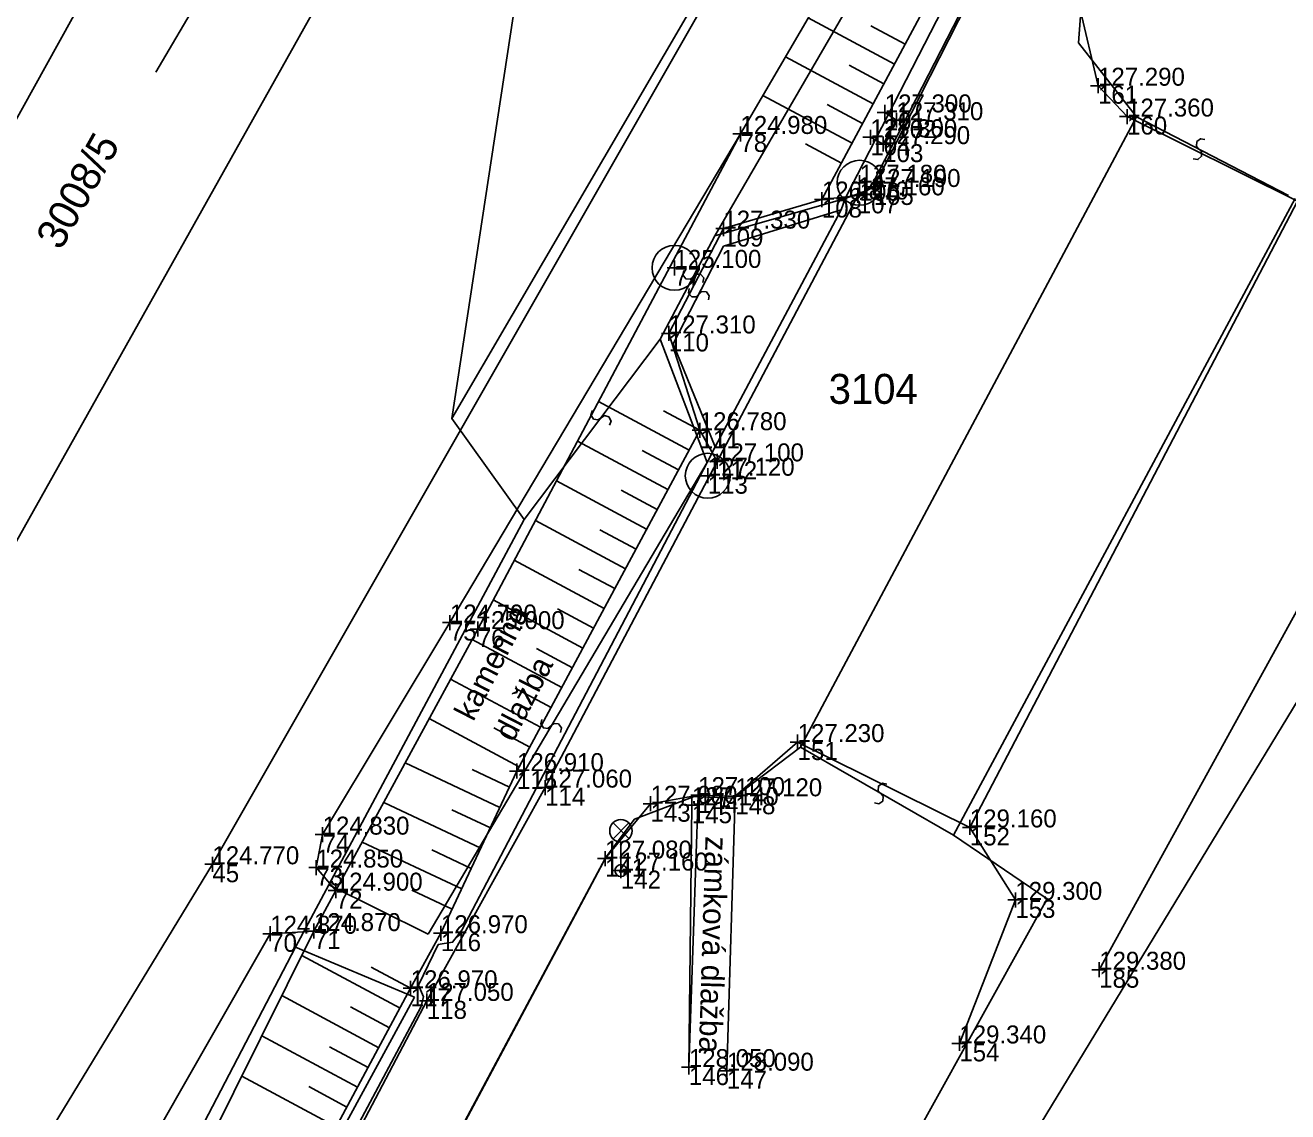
# Model space of a CAD drawing. Extents: x -747268 to -747054, y -964730 to -964532.
# Drawn here: x -747222.18 to -747180.02, y -964669.15 to -964632.88 of the extents above; entities that cross this region are included whole.
import ezdxf

# ---------------------------------------------------------------- set-up
doc = ezdxf.new("R2010")
doc.units = 0
for name, color, linetype in [('Body polohopisu', 7, 'Continuous'), ('Doplňkové značky', 7, 'Continuous'), ('KM', 7, 'Continuous'), ('Ploty_opěrné zdi', 7, 'Continuous'), ('Popisy objektů_povrchů', 7, 'Continuous'), ('Rozhraní ploch', 7, 'Continuous'), ('Vnitřní kresba', 7, 'Continuous'), ('Výškopis', 7, 'Continuous'), ('Výšky bodů', 7, 'Continuous'), ('Značky IS', 7, 'Continuous'), ('Čísla bodů', 7, 'Continuous')]:
    doc.layers.add(name, color=color, linetype=linetype)

msp = doc.modelspace()

# ---------------------------------------------------------------- linework, layer by layer
at = {"layer": 'Body polohopisu'}
for p, q in [((-747186.36, -964634.9), (-747186.36, -964634.65)), ((-747186.36, -964634.9), (-747186.61, -964634.9)), ((-747186.36, -964634.9), (-747186.11, -964634.9)), ((-747186.36, -964634.9), (-747186.36, -964635.15)), ((-747193.48, -964635.79), (-747193.48, -964635.54)), ((-747185.39, -964635.93), (-747185.39, -964635.68)), ((-747193.48, -964635.79), (-747193.73, -964635.79)), ((-747193.48, -964635.79), (-747193.23, -964635.79)), ((-747193.48, -964635.79), (-747193.48, -964636.04)), ((-747193.09, -964636.05), (-747193.34, -964636.05)), ((-747193.09, -964636.05), (-747193.09, -964635.8)), ((-747193.09, -964636.05), (-747192.84, -964636.05)), ((-747193.09, -964636.05), (-747193.09, -964636.3)), ((-747185.39, -964635.93), (-747185.64, -964635.93)), ((-747185.39, -964635.93), (-747185.14, -964635.93)), ((-747185.39, -964635.93), (-747185.39, -964636.18)), ((-747198.3, -964636.51), (-747198.55, -964636.51)), ((-747198.3, -964636.51), (-747198.3, -964636.26)), ((-747198.3, -964636.51), (-747198.05, -964636.51)), ((-747198.3, -964636.51), (-747198.3, -964636.76)), ((-747193.96, -964636.62), (-747193.96, -964636.37)), ((-747193.96, -964636.62), (-747194.21, -964636.62)), ((-747193.96, -964636.62), (-747193.71, -964636.62)), ((-747193.96, -964636.62), (-747193.96, -964636.87)), ((-747193.53, -964636.85), (-747193.78, -964636.85)), ((-747193.53, -964636.85), (-747193.53, -964636.6)), ((-747193.53, -964636.85), (-747193.28, -964636.85)), ((-747193.53, -964636.85), (-747193.53, -964637.1)), ((-747194.32, -964638.14), (-747194.57, -964638.14)), ((-747194.32, -964638.14), (-747194.32, -964637.89)), ((-747194.32, -964638.14), (-747194.07, -964638.14)), ((-747194.32, -964638.14), (-747194.32, -964638.39)), ((-747193.85, -964638.28), (-747193.85, -964638.03)), ((-747195.58, -964638.7), (-747195.58, -964638.45)), ((-747194.38, -964638.56), (-747194.63, -964638.56)), ((-747194.38, -964638.56), (-747194.38, -964638.31)), ((-747194.38, -964638.56), (-747194.13, -964638.56)), ((-747194.38, -964638.56), (-747194.38, -964638.81)), ((-747193.85, -964638.28), (-747194.1, -964638.28)), ((-747193.85, -964638.28), (-747193.6, -964638.28)), ((-747193.85, -964638.28), (-747193.85, -964638.53)), ((-747195.58, -964638.7), (-747195.83, -964638.7)), ((-747195.58, -964638.7), (-747195.33, -964638.7)), ((-747195.58, -964638.7), (-747195.58, -964638.95)), ((-747198.87, -964639.67), (-747198.87, -964639.42)), ((-747198.87, -964639.67), (-747199.12, -964639.67)), ((-747198.87, -964639.67), (-747198.62, -964639.67)), ((-747198.87, -964639.67), (-747198.87, -964639.92)), ((-747200.5, -964640.98), (-747200.5, -964640.73)), ((-747200.5, -964640.98), (-747200.75, -964640.98)), ((-747200.5, -964640.98), (-747200.25, -964640.98)), ((-747200.5, -964640.98), (-747200.5, -964641.23)), ((-747200.69, -964643.17), (-747200.94, -964643.17)), ((-747200.69, -964643.17), (-747200.69, -964642.92)), ((-747200.69, -964643.17), (-747200.44, -964643.17)), ((-747200.69, -964643.17), (-747200.69, -964643.42)), ((-747199.66, -964646.4), (-747199.66, -964646.15)), ((-747199.66, -964646.4), (-747199.91, -964646.4)), ((-747199.66, -964646.4), (-747199.41, -964646.4)), ((-747199.66, -964646.4), (-747199.66, -964646.65)), ((-747199.08, -964647.44), (-747199.33, -964647.44)), ((-747199.08, -964647.44), (-747199.08, -964647.19)), ((-747199.08, -964647.44), (-747198.83, -964647.44)), ((-747199.08, -964647.44), (-747199.08, -964647.69)), ((-747199.39, -964647.92), (-747199.64, -964647.92)), ((-747199.39, -964647.92), (-747199.39, -964647.67)), ((-747199.39, -964647.92), (-747199.14, -964647.92)), ((-747199.39, -964647.92), (-747199.39, -964648.17)), ((-747208, -964652.82), (-747208, -964652.57)), ((-747208, -964652.82), (-747208.25, -964652.82)), ((-747208, -964652.82), (-747207.75, -964652.82)), ((-747208, -964652.82), (-747208, -964653.07)), ((-747207.07, -964653.04), (-747207.07, -964652.79)), ((-747207.07, -964653.04), (-747207.32, -964653.04)), ((-747207.07, -964653.04), (-747206.82, -964653.04)), ((-747207.07, -964653.04), (-747207.07, -964653.29)), ((-747196.39, -964656.81), (-747196.39, -964656.56)), ((-747196.39, -964656.81), (-747196.64, -964656.81)), ((-747196.39, -964656.81), (-747196.14, -964656.81)), ((-747196.39, -964656.81), (-747196.39, -964657.06)), ((-747205.76, -964657.78), (-747205.76, -964657.53)), ((-747205.76, -964657.78), (-747206.01, -964657.78)), ((-747205.76, -964657.78), (-747205.51, -964657.78)), ((-747205.76, -964657.78), (-747205.76, -964658.03)), ((-747204.82, -964658.33), (-747205.07, -964658.33)), ((-747204.82, -964658.33), (-747204.82, -964658.08)), ((-747204.82, -964658.33), (-747204.57, -964658.33)), ((-747204.82, -964658.33), (-747204.82, -964658.58)), ((-747199.71, -964658.58), (-747199.71, -964658.33)), ((-747198.47, -964658.62), (-747198.47, -964658.37)), ((-747201.3, -964658.87), (-747201.55, -964658.87)), ((-747201.3, -964658.87), (-747201.3, -964658.62)), ((-747201.3, -964658.87), (-747201.05, -964658.87)), ((-747201.3, -964658.87), (-747201.3, -964659.12)), ((-747199.71, -964658.58), (-747199.96, -964658.58)), ((-747199.92, -964658.92), (-747199.92, -964658.67)), ((-747199.71, -964658.58), (-747199.46, -964658.58)), ((-747199.71, -964658.58), (-747199.71, -964658.83)), ((-747198.47, -964658.62), (-747198.72, -964658.62)), ((-747198.47, -964658.62), (-747198.22, -964658.62)), ((-747198.47, -964658.62), (-747198.47, -964658.87)), ((-747199.92, -964658.92), (-747200.17, -964658.92)), ((-747199.92, -964658.92), (-747199.67, -964658.92)), ((-747199.92, -964658.92), (-747199.92, -964659.17)), ((-747212.25, -964659.9), (-747212.25, -964659.65)), ((-747190.64, -964659.66), (-747190.89, -964659.66)), ((-747190.64, -964659.66), (-747190.64, -964659.41)), ((-747190.64, -964659.66), (-747190.39, -964659.66)), ((-747190.64, -964659.66), (-747190.64, -964659.91)), ((-747212.25, -964659.9), (-747212.5, -964659.9)), ((-747212.25, -964659.9), (-747212, -964659.9)), ((-747212.25, -964659.9), (-747212.25, -964660.15)), ((-747202.82, -964660.7), (-747202.82, -964660.45)), ((-747215.93, -964660.89), (-747216.18, -964660.89)), ((-747215.93, -964660.89), (-747215.93, -964660.64)), ((-747215.93, -964660.89), (-747215.68, -964660.89)), ((-747215.93, -964660.89), (-747215.93, -964661.14)), ((-747212.46, -964661), (-747212.71, -964661)), ((-747212.46, -964661), (-747212.46, -964660.75)), ((-747212.46, -964661), (-747212.21, -964661)), ((-747212.46, -964661), (-747212.46, -964661.25)), ((-747202.82, -964660.7), (-747203.07, -964660.7)), ((-747202.82, -964660.7), (-747202.57, -964660.7)), ((-747202.82, -964660.7), (-747202.82, -964660.95)), ((-747202.29, -964661.1), (-747202.29, -964660.85)), ((-747202.29, -964661.1), (-747202.54, -964661.1)), ((-747202.29, -964661.1), (-747202.04, -964661.1)), ((-747202.29, -964661.1), (-747202.29, -964661.35)), ((-747211.81, -964661.77), (-747212.06, -964661.77)), ((-747211.81, -964661.77), (-747211.81, -964661.52)), ((-747211.81, -964661.77), (-747211.56, -964661.77)), ((-747211.81, -964661.77), (-747211.81, -964662.02)), ((-747189.12, -964662.08), (-747189.12, -964661.83)), ((-747189.12, -964662.08), (-747189.37, -964662.08)), ((-747189.12, -964662.08), (-747188.87, -964662.08)), ((-747189.12, -964662.08), (-747189.12, -964662.33)), ((-747214, -964663.21), (-747214, -964662.96)), ((-747212.54, -964663.12), (-747212.54, -964662.87)), ((-747208.3, -964663.19), (-747208.3, -964662.94)), ((-747214, -964663.21), (-747214.25, -964663.21)), ((-747214, -964663.21), (-747213.75, -964663.21)), ((-747214, -964663.21), (-747214, -964663.46)), ((-747212.54, -964663.12), (-747212.79, -964663.12)), ((-747212.54, -964663.12), (-747212.29, -964663.12)), ((-747212.54, -964663.12), (-747212.54, -964663.37)), ((-747208.3, -964663.19), (-747208.55, -964663.19)), ((-747208.3, -964663.19), (-747208.05, -964663.19)), ((-747208.3, -964663.19), (-747208.3, -964663.44)), ((-747186.32, -964664.41), (-747186.32, -964664.16)), ((-747209.31, -964665.03), (-747209.31, -964664.78)), ((-747186.32, -964664.41), (-747186.57, -964664.41)), ((-747186.32, -964664.41), (-747186.07, -964664.41)), ((-747186.32, -964664.41), (-747186.32, -964664.66)), ((-747209.31, -964665.03), (-747209.56, -964665.03)), ((-747209.31, -964665.03), (-747209.06, -964665.03)), ((-747209.31, -964665.03), (-747209.31, -964665.28)), ((-747208.77, -964665.45), (-747208.77, -964665.2)), ((-747208.77, -964665.45), (-747209.02, -964665.45)), ((-747208.77, -964665.45), (-747208.52, -964665.45)), ((-747208.77, -964665.45), (-747208.77, -964665.7)), ((-747190.99, -964666.87), (-747191.24, -964666.87)), ((-747190.99, -964666.87), (-747190.99, -964666.62)), ((-747190.99, -964666.87), (-747190.74, -964666.87)), ((-747190.99, -964666.87), (-747190.99, -964667.12)), ((-747200.02, -964667.66), (-747200.27, -964667.66)), ((-747200.02, -964667.66), (-747200.02, -964667.41)), ((-747200.02, -964667.66), (-747199.77, -964667.66)), ((-747200.02, -964667.66), (-747200.02, -964667.91)), ((-747198.75, -964667.78), (-747198.75, -964667.53)), ((-747198.75, -964667.78), (-747199, -964667.78)), ((-747198.75, -964667.78), (-747198.5, -964667.78)), ((-747198.75, -964667.78), (-747198.75, -964668.03))]:
    msp.add_line(p, q, dxfattribs=at)
at = {"layer": 'Doplňkové značky'}
for p, q in [((-747202.554, -964660.038), (-747202.026, -964659.51)), ((-747202.018, -964660.035), (-747202.546, -964659.506)), ((-747202.29, -964660.15), (-747202.29, -964660.9))]:
    msp.add_line(p, q, dxfattribs=at)
for centre, radius in [((-747202.29, -964659.775), 0.375), ((-747202.29, -964661.1), 0.2)]:
    msp.add_circle(centre, radius, dxfattribs=at)
at = {"layer": 'KM'}
msp.add_line((-747217.82, -964634.444), (-747216.296, -964631.86), dxfattribs=at)
for points in [[(-747258.428, -964718.402), (-747225.89, -964656.18), (-747178.58, -964571.79), (-747161.768, -964542.826)], [(-747245.973, -964725.574), (-747237.39, -964710.13), (-747213.15, -964663.66), (-747212.04, -964661.58), (-747205.52, -964649.38), (-747207.93, -964646.01), (-747172.64, -964585.56), (-747171.18, -964583.16), (-747172.38, -964582.51), (-747172.75, -964582.31), (-747169.52, -964576.73), (-747168.08, -964577.53), (-747165.21, -964574.13), (-747160.86, -964564.14), (-747155.16, -964551.47), (-747155.48, -964551.37), (-747155.09, -964550.12), (-747154.28, -964550.33), (-747154.06, -964549.5), (-747153.365, -964547.044)], [(-747242.047, -964727.609), (-747230.16, -964705.36), (-747208.97, -964665.66), (-747208.88, -964665.32), (-747209.05, -964664.92), (-747208.39, -964663.57), (-747207.91, -964663.49), (-747207.6, -964663.09), (-747199.41, -964647.48), (-747199.14, -964646.95), (-747194.94, -964639.04), (-747194.8, -964638.66), (-747194.08, -964638.4), (-747193.89, -964638.17), (-747178.12, -964607.48), (-747165.52, -964582.92), (-747162.81, -964577.62), (-747161.38, -964574.2), (-747160.49, -964571.42), (-747153.77, -964550.39), (-747154.12, -964550.42), (-747153.81, -964549.44), (-747153.109, -964547.254)], [(-747149.729, -964549.086), (-747149.93, -964549.71), (-747150.35, -964549.8), (-747157.75, -964573.23), (-747158.53, -964575.6), (-747159.7, -964578.37), (-747163.23, -964585.33), (-747175.42, -964609.03), (-747186.84, -964631.22), (-747187.01, -964633.47), (-747185.08, -964635.94), (-747196.29, -964656.98), (-747198.54, -964658.68), (-747199.84, -964658.63), (-747201.84, -964659.38), (-747202.78, -964660.64), (-747203.73, -964662.42), (-747219.36, -964691.72)], [(-747179.78, -964638.67), (-747191.19, -964659.92), (-747188.06, -964662.04), (-747194.37, -964673.41)], [(-747170.03, -964639.52), (-747191.65, -964675.11), (-747205.07, -964701.27), (-747194.33, -964694.71), (-747168.43, -964681.69), (-747141.95, -964674.74), (-747119.57, -964669.71), (-747114.21, -964668.06), (-747110.99, -964665.85), (-747107.13, -964660.6)]]:
    msp.add_lwpolyline(points, dxfattribs=at)
at = {"layer": 'Ploty_opěrné zdi'}
for points in [[(-747194.38, -964638.56), (-747195.58, -964638.7), (-747198.87, -964639.67), (-747200.69, -964643.17), (-747199.66, -964646.4), (-747199.08, -964647.44)], [(-747199.92, -964658.92), (-747200.02, -964667.66)]]:
    msp.add_lwpolyline(points, dxfattribs=at)
at = {"layer": 'Rozhraní ploch'}
msp.add_line((-747199.71, -964658.58), (-747198.47, -964658.62), dxfattribs=at)
for points in [[(-747164.8, -964581.46), (-747168.98, -964589.75), (-747182.91, -964616.97), (-747186.63, -964624.1), (-747193.85, -964638.28), (-747194.38, -964638.56), (-747199.08, -964647.44), (-747204.82, -964658.33), (-747208.77, -964665.45), (-747214.7, -964676.73), (-747220.35, -964687.31), (-747228.95, -964703.36)], [(-747185.39, -964635.93), (-747186.36, -964634.9), (-747186.99, -964632.21), (-747186.48, -964630.65), (-747183.82, -964625.34), (-747180.07, -964618.31), (-747170.65, -964599.99), (-747161.67, -964582.51), (-747155.9, -964583.06)], [(-747211.81, -964661.77), (-747212.46, -964661), (-747212.25, -964659.9), (-747208, -964652.82), (-747198.3, -964636.51), (-747191.97, -964625.69), (-747187.47, -964617.82), (-747186.88, -964617)], [(-747207.74, -964618.01), (-747209.42, -964620.7), (-747207.13, -964621.42), (-747205.64, -964619.2), (-747202.99, -964624.62), (-747199.45, -964632.07), (-747215.93, -964660.89), (-747224.57, -964675.08), (-747231.76, -964687.56), (-747236.28, -964694.89), (-747237.94, -964696.27), (-747242.26, -964695.59), (-747246.85, -964693), (-747247.82, -964691.84), (-747248.23, -964692.9)], [(-747168.85, -964633.1), (-747178.33, -964649.9), (-747186.32, -964664.41)], [(-747196.39, -964656.81), (-747190.64, -964659.66), (-747179.7, -964638.75), (-747185.39, -964635.93)], [(-747198.75, -964667.78), (-747198.47, -964658.62), (-747196.39, -964656.81)], [(-747212.14, -964686.73), (-747218.44, -964691.02), (-747219.46, -964691.87), (-747209.93, -964674.01), (-747202.82, -964660.7), (-747201.3, -964658.87), (-747199.71, -964658.58), (-747200.02, -964667.66)], [(-747190.64, -964659.66), (-747189.12, -964662.08), (-747190.99, -964666.87)], [(-747212.54, -964663.12), (-747211.81, -964661.77)], [(-747232.9, -964701.27), (-747235.02, -964700.23), (-747229.96, -964690.49), (-747220.4, -964674.42), (-747214, -964663.21), (-747212.54, -964663.12)], [(-747208.3, -964663.19), (-747209.31, -964665.03)]]:
    msp.add_lwpolyline(points, dxfattribs=at)
at = {"layer": 'Vnitřní kresba'}
for p, q in [((-747231.87, -964652.97), (-747184.5, -964567.43)), ((-747199.15, -964639.91), (-747166.09, -964582.82)), ((-747166.09, -964582.82), (-747194.8, -964638.66)), ((-747205.66, -964631.1), (-747207.93, -964646.01)), ((-747185.08, -964635.94), (-747180, -964638.56)), ((-747194.8, -964638.66), (-747199.15, -964639.91)), ((-747194.94, -964639.04), (-747198.87, -964640.26)), ((-747199.15, -964639.91), (-747200.98, -964643.36)), ((-747200.54, -964643.52), (-747198.87, -964640.26)), ((-747205.52, -964649.38), (-747200.98, -964643.36)), ((-747200.98, -964643.36), (-747199.41, -964647.48)), ((-747199.14, -964646.95), (-747200.54, -964643.52)), ((-747199.41, -964647.48), (-747208.73, -964663.22)), ((-747191.19, -964659.92), (-747196.29, -964656.98)), ((-747208.73, -964663.22), (-747212.04, -964661.58)), ((-747213.15, -964663.66), (-747209.18, -964665.33)), ((-747209.18, -964665.33), (-747244.025, -964729.117))]:
    msp.add_line(p, q, dxfattribs=at)
for points in [[(-747183.18, -964637.342), (-747183.024, -964637.366), (-747182.9, -964637.256), (-747182.9, -964637.104), (-747183.074, -964636.918), (-747183.063, -964636.766), (-747182.935, -964636.67), (-747182.792, -964636.698)], [(-747199.552, -964641.469), (-747199.526, -964641.313), (-747199.635, -964641.187), (-747199.787, -964641.186), (-747199.975, -964641.358), (-747200.127, -964641.345), (-747200.222, -964641.216), (-747200.192, -964641.073)], [(-747200.011, -964641.666), (-747200.035, -964641.822), (-747199.925, -964641.946), (-747199.773, -964641.945), (-747199.588, -964641.771), (-747199.436, -964641.781), (-747199.338, -964641.909), (-747199.367, -964642.052)], [(-747203.242, -964645.737), (-747203.293, -964645.887), (-747203.205, -964646.028), (-747203.055, -964646.054), (-747202.843, -964645.913), (-747202.695, -964645.95), (-747202.621, -964646.093), (-747202.674, -964646.229)], [(-747204.308, -964656.488), (-747204.275, -964656.333), (-747204.377, -964656.202), (-747204.529, -964656.194), (-747204.725, -964656.357), (-747204.876, -964656.337), (-747204.965, -964656.203), (-747204.928, -964656.062)], [(-747193.406, -964658.21), (-747193.561, -964658.178), (-747193.69, -964658.282), (-747193.697, -964658.434), (-747193.532, -964658.628), (-747193.55, -964658.779), (-747193.683, -964658.87), (-747193.824, -964658.834)]]:
    msp.add_lwpolyline(points, dxfattribs=at)
at = {"layer": 'Výškopis'}
for points in [[(-747211.81, -964661.77), (-747207.07, -964653.04), (-747198.3, -964636.51), (-747191.97, -964625.69), (-747187.47, -964617.82)], [(-747186.19, -964620.08), (-747187.72, -964624.04), (-747195.58, -964638.7)], [(-747193.156, -964634.179), (-747196.034, -964632.636)], [(-747192.802, -964633.518), (-747193.943, -964632.906)], [(-747193.865, -964635.501), (-747196.792, -964633.932)], [(-747193.511, -964634.84), (-747194.672, -964634.218)], [(-747194.574, -964636.823), (-747197.55, -964635.228)], [(-747194.219, -964636.162), (-747195.4, -964635.529)], [(-747194.928, -964637.484), (-747196.128, -964636.841)], [(-747200.014, -964647.061), (-747203.038, -964645.44)], [(-747199.66, -964646.4), (-747200.871, -964645.751)], [(-747199.66, -964646.4), (-747205.76, -964657.78), (-747208.3, -964663.19)], [(-747200.723, -964648.383), (-747203.741, -964646.765)], [(-747200.369, -964647.722), (-747201.577, -964647.074)], [(-747201.432, -964649.705), (-747204.444, -964648.09)], [(-747201.077, -964649.044), (-747202.283, -964648.398)], [(-747202.14, -964651.027), (-747205.147, -964649.415)], [(-747201.786, -964650.366), (-747202.99, -964649.721)], [(-747202.849, -964652.349), (-747205.85, -964650.741)], [(-747202.495, -964651.688), (-747203.696, -964651.044)], [(-747203.558, -964653.671), (-747206.553, -964652.066)], [(-747203.203, -964653.01), (-747204.403, -964652.367)], [(-747204.266, -964654.993), (-747207.259, -964653.389)], [(-747203.912, -964654.332), (-747205.109, -964653.691)], [(-747204.975, -964656.315), (-747207.975, -964654.707)], [(-747204.621, -964655.654), (-747205.819, -964655.012)], [(-747205.684, -964657.637), (-747208.691, -964656.025)], [(-747205.329, -964656.976), (-747206.531, -964656.332)], [(-747206.329, -964658.991), (-747209.494, -964657.505)], [(-747206.01, -964658.312), (-747207.26, -964657.725)], [(-747206.966, -964660.349), (-747210.211, -964658.826)], [(-747206.647, -964659.67), (-747207.93, -964659.068)], [(-747207.604, -964661.707), (-747210.928, -964660.146)], [(-747207.285, -964661.028), (-747208.599, -964660.411)], [(-747207.922, -964662.386), (-747209.268, -964661.754)], [(-747232.9, -964701.27), (-747227.21, -964691.41), (-747218.79, -964675.69), (-747212.54, -964663.12)], [(-747209.665, -964665.691), (-747212.943, -964663.931)], [(-747209.31, -964665.03), (-747210.63, -964664.322)], [(-747209.31, -964665.03), (-747215.42, -964676.41), (-747220.94, -964686.92), (-747229.61, -964702.9)], [(-747210.374, -964667.012), (-747213.611, -964665.274)], [(-747210.02, -964666.352), (-747211.323, -964665.652)], [(-747211.084, -964668.334), (-747214.279, -964666.618)], [(-747210.729, -964667.673), (-747212.016, -964666.982)], [(-747211.793, -964669.655), (-747214.948, -964667.962)], [(-747211.439, -964668.995), (-747212.709, -964668.313)]]:
    msp.add_lwpolyline(points, dxfattribs=at)
at = {"layer": 'Značky IS'}
msp.add_lwpolyline([(-747193.48, -964635.79), (-747193.09, -964636.05), (-747193.53, -964636.85), (-747193.96, -964636.62)], dxfattribs=at)
for centre in [(-747194.32, -964638.14), (-747200.5, -964640.98), (-747199.39, -964647.92)]:
    msp.add_circle(centre, 0.75, dxfattribs=at)

# ---------------------------------------------------------------- texts
at = {"layer": 'KM'}
msp.add_text('3008/5', height=1, rotation=60.7245, dxfattribs=at).set_placement((-747220.994, -964640.428))
msp.add_text('3104', height=1, dxfattribs=at).set_placement((-747195.352, -964645.52))
at = {"layer": 'Popisy objektů_povrchů'}
for s, rotation, p in [('kamenná', 62.7676, (-747207.22, -964656.149)), ('dlažba', 62.7676, (-747205.886, -964656.836)), ('zámková dlažba', 268.2491, (-747199.465, -964659.945))]:
    msp.add_text(s, height=0.75, rotation=rotation, dxfattribs=at).set_placement(p)
at = {"layer": 'Výšky bodů'}
for s, p in [('127.290', (-747186.36, -964634.9)), ('127.300', (-747193.48, -964635.79)), ('127.310', (-747193.09, -964636.05)), ('127.360', (-747185.39, -964635.93)), ('124.980', (-747198.3, -964636.51)), ('127.300', (-747193.96, -964636.62)), ('127.290', (-747193.53, -964636.85)), ('127.180', (-747194.32, -964638.14)), ('127.190', (-747193.85, -964638.28)), ('126.870', (-747195.58, -964638.7)), ('127.160', (-747194.38, -964638.56)), ('127.330', (-747198.87, -964639.67)), ('125.100', (-747200.5, -964640.98)), ('127.310', (-747200.69, -964643.17)), ('126.780', (-747199.66, -964646.4)), ('127.100', (-747199.08, -964647.44)), ('127.120', (-747199.39, -964647.92)), ('124.790', (-747208, -964652.82)), ('125.000', (-747207.07, -964653.04)), ('127.230', (-747196.39, -964656.81)), ('126.910', (-747205.76, -964657.78)), ('127.060', (-747204.82, -964658.33)), ('127.100', (-747199.71, -964658.58)), ('127.120', (-747198.47, -964658.62)), ('127.080', (-747201.3, -964658.87)), ('127.140', (-747199.92, -964658.92)), ('124.830', (-747212.25, -964659.9)), ('129.160', (-747190.64, -964659.66)), ('127.080', (-747202.82, -964660.7)), ('124.770', (-747215.93, -964660.89)), ('124.850', (-747212.46, -964661)), ('127.160', (-747202.29, -964661.1)), ('124.900', (-747211.81, -964661.77)), ('129.300', (-747189.12, -964662.08)), ('124.870', (-747214, -964663.21)), ('124.870', (-747212.54, -964663.12)), ('126.970', (-747208.3, -964663.19)), ('129.380', (-747186.32, -964664.41)), ('126.970', (-747209.31, -964665.03)), ('127.050', (-747208.77, -964665.45)), ('129.340', (-747190.99, -964666.87)), ('128.050', (-747200.02, -964667.66)), ('128.090', (-747198.75, -964667.78))]:
    msp.add_text(s, height=0.6, dxfattribs=at).set_placement(p)
at = {"layer": 'Čísla bodů'}
for s, p in [('161', (-747186.36, -964635.5)), ('101', (-747193.48, -964636.39)), ('102', (-747193.09, -964636.65)), ('160', (-747185.39, -964636.53)), ('78', (-747198.3, -964637.11)), ('104', (-747193.96, -964637.22)), ('103', (-747193.53, -964637.45)), ('106', (-747194.32, -964638.74)), ('107', (-747194.38, -964639.16)), ('105', (-747193.85, -964638.88)), ('108', (-747195.58, -964639.3)), ('109', (-747198.87, -964640.27)), ('77', (-747200.5, -964641.58)), ('110', (-747200.69, -964643.77)), ('111', (-747199.66, -964647)), ('112', (-747199.08, -964648.04)), ('113', (-747199.39, -964648.52)), ('75', (-747208, -964653.42)), ('76', (-747207.07, -964653.64)), ('151', (-747196.39, -964657.41)), ('115', (-747205.76, -964658.38)), ('114', (-747204.82, -964658.93)), ('143', (-747201.3, -964659.47)), ('144', (-747199.71, -964659.18)), ('148', (-747198.47, -964659.22)), ('145', (-747199.92, -964659.52)), ('152', (-747190.64, -964660.26)), ('74', (-747212.25, -964660.5)), ('45', (-747215.93, -964661.49)), ('73', (-747212.46, -964661.6)), ('141', (-747202.82, -964661.3)), ('142', (-747202.29, -964661.7)), ('72', (-747211.81, -964662.37)), ('153', (-747189.12, -964662.68)), ('70', (-747214, -964663.81)), ('71', (-747212.54, -964663.72)), ('116', (-747208.3, -964663.79)), ('185', (-747186.32, -964665.01)), ('117', (-747209.31, -964665.63)), ('118', (-747208.77, -964666.05)), ('154', (-747190.99, -964667.47)), ('146', (-747200.02, -964668.26)), ('147', (-747198.75, -964668.38))]:
    msp.add_text(s, height=0.6, dxfattribs=at).set_placement(p)

doc.saveas('drawing.dxf')
